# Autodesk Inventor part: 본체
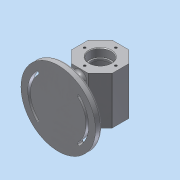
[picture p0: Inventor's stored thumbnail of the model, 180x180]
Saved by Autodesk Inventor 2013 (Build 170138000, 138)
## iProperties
Created: 2017-06
Part Number: 본체
Material: 알루미늄 6061
Document SubType Name: Modeling
Designer: dgall
Density: 2.71 g/cm^3
Mass: 562.296 g
Surface Area: 566.36 cm^2
Volume: 207.489 cm^3
Author: dgall
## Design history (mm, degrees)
sketch "스케치1"
  geometry: L1 (-30, 12.426)-(-12.426, 30); L2 (-12.426, 30)-(12.426, 30); L3 (12.426, 30)-(30, 12.426); L4 (30, 12.426)-(30, -12.426); L5 (30, -12.426)-(12.426, -30); L6 (12.426, -30)-(-12.426, -30); L7 (-12.426, -30)-(-30, -12.426); L8 (-30, -12.426)-(-30, 12.426); 2 further points
  constraints: 16 end point, 1 coincident, 1 vertical, 17 other
  dimensions: "d0" = 30 distance from line of L8 point (0, 0)
extrude "돌출1" new body sketch "스케치1" distance "d1" = 70; taper "d2" = 0 deg
sketch "스케치2"
  geometry: L1 (30, 70)-(12.426, 70) reference; L2 (12.426, 70)-(-12.426, 70) reference; L3 (12.426, 0)-(30, 0) reference; L4 (-12.426, 0)-(12.426, 0) reference; L5 (-30, 0)-(-12.426, 0) reference; L6 (-30, 0)-(-30, 70) reference; L7 (0, 0)-(0, 70); L8 (16, 58)-(14, 58); L9 (14, 58)-(14, 55); L10 (14, 55)-(22, 55); L11 (25, 52)-(25, 18); L12 (22, 15)-(14, 15); L13 (14, 15)-(14, 12); L14 (16, 70)-(16, 58); L15 (14, 12)-(16, 12); L16 (16, 12)-(16, 0); L17 (16, 70)-(30, 70); L18 (30, 0)-(16, 0); L19 (30, 0)-(30, 70); L20 (16, 70)-(0, 70); L21 (16, 0)-(0, 0); A1 r 3 centre (22, 52) between (25, 52) and (22, 55); A2 r 3 centre (22, 18) between (22, 15) and (25, 18)
  constraints: 30 end point, 4 collinear, 4 perpendicular, 4 point on circle, 4 point on line, 4 tangent, 3 parallel, 2 centre point, 2 vertical alignment, 1 equal radius, 1 midpoint
  dimensions: "d4" = 28 diameter of L9 L7; "d6" = 32 diameter of L14 L7; "d7" = 50 diameter of L11 L7; "d8" = 12 distance between parallel lines of L8 L2; "d10" = 40 distance between parallel lines of L12 L10; "d12" = 3 distance between parallel lines of L15 L12; "d13" = 3 radius of A1; "d14" = 60 diameter of L19 L7
revolve "회전1" sketch "스케치2" stored, may be unused: angle "d15" = 90 deg
node "작업 평면1"
sketch "스케치4"
  geometry: L1 (-30, 0)-(-30, 70) reference; L2 (30, 0)-(30, 70) reference; L3 (-12.426, 70)-(12.426, 70) reference; L4 (12.426, 0)-(-12.426, 0) reference; C1 r 55 at (0, 35); 2 further points
  constraints: 1 centre point, 1 midpoint, 1 vertical alignment
  dimensions: "d17" = 110 diameter of C1; "d18" = 35 distance from line of C1.centre L4
extrude "돌출2" join sketch "스케치4" distance "d19" = 10; taper "d20" = 0 deg
sketch "스케치6"
  geometry: L1 (30.406, 30.406)-(0, 0); L2 (0, 0)-(30.406, -30.406); L3 (0, 0)-(55, 0); A1 r 5 centre (30.406, 30.406) between (33.941, 33.941) and (26.87, 26.87); A2 r 48 centre (0, 0) between (33.941, -33.941) and (33.941, 33.941); A3 r 38 centre (0, 0) between (26.87, -26.87) and (26.87, 26.87); A4 r 5 centre (30.406, -30.406) between (26.87, -26.87) and (33.941, -33.941); A5 r 2 centre (30.406, 30.406) between (31.82, 31.82) and (28.991, 28.991); A6 r 41 centre (0, 0) between (28.991, -28.991) and (28.991, 28.991); A7 r 2 centre (30.406, -30.406) between (28.991, -28.991) and (31.82, -31.82); A8 r 45 centre (0, 0) between (31.82, -31.82) and (31.82, 31.82); 1 further point
  constraints: 16 point on circle, 8 centre point, 6 end point, 4 tangent, 2 coincident, 1 equal radius, 1 horizontal, 1 horizontal alignment, 1 perpendicular, 4 other
  dimensions: "d30" = 90 deg angle of L2 L1; "d31" = 45 deg angle of L3 L1; "d32" = 5 radius of A1; "d34" = 43 distance of L1.start L1.end; "d35" = 2 radius of A5
extrude "돌출3" cut sketch "스케치6" stored distance "d36" = 0; taper "d37" = 0 deg
extrude "돌출4" cut sketch "스케치6" distance "d38" = 3; taper "d39" = 0 deg
sketch "스케치7"
  geometry: L1 (-5, 24)-(-5, -24); L2 (5, -24)-(5, 24); A1 r 38 centre (0, 0) between (26.87, -26.87) and (26.87, 26.87) reference; A2 r 5 centre (0, -24) between (-5, -24) and (5, -24); A3 r 5 centre (0, 24) between (5, 24) and (-5, 24); 2 further points
  constraints: 4 end point, 4 point on circle, 4 tangent, 2 centre point, 2 vertical, 1 horizontal alignment, 1 midpoint, 1 vertical alignment
  dimensions: "d40" = 48 distance of A2.centre A3.centre; "d42" = 5 radius of A3
extrude "돌출5" join sketch "스케치7" stored distance "d43" = 0; taper "d44" = 0 deg
fillet "모깎기1" dims "d45" = 5
fillet "모깎기2" dims "d46" = 0.3
chamfer "모따기1" distance "d47" = 1; stored, may be unused: second distance "d48" = 2, angle "d49" = 45 deg
sketch "스케치8"
  geometry: C1 r 17 at (0, 0) reference; 1 further point
  constraints: 1 vertical alignment
  dimensions: "d50" = 23 distance of point (0, 23) C1.centre
hole "구멍1" sketch "스케치8" at (0, 23) diameter "d51" = 3.459; stored, may be unused: countersink angle "d55" = 90 deg, drill point angle "d57" = 118 deg; dims "d52" = 8, "d53" = 4, "d54" = 2, "d56" = 10
node "작업 평면2"
sketch "스케치9"
  geometry: L1 (42.426, 0)-(42.426, -70) reference; 2 further points
  constraints: 1 other
  dimensions: "d61" = 35 distance of point (12.426, -35) point (12.426, 0); "d62" = 30 distance from line of point (12.426, -35) L1
feature "엠보싱1" sketch "스케치9" dims "d0" = 30, "d4" = 28, "d6" = 32, "d7" = 50, "d8" = 12, "d10" = 40, "d12" = 3, "d13" = 3, "d14" = 60, "d63" = 0.5, "d64" = 0
sketch "스케치13"
  geometry: L1 (0, 0)-(-24.853, 0) reference; L2 (-42.426, 0)-(-42.426, 70) reference; C1 r 8 at (-12.426, 35); 1 further point
  constraints: 1 centre point
  dimensions: "d79" = 16 diameter of C1; "d80" = 35 distance from line of C1.centre L1; "d81" = 30 distance from line of C1.centre L2
extrude "돌출7" join sketch "스케치13" distance "d82" = 7; taper "d83" = 0 deg
sketch "스케치14"
  geometry: C1 r 8 at (0, 0) reference; 2 further points
  constraints: 1 coincident
hole "구멍3" sketch "스케치14" at (0, 0) diameter "d84" = 8; stored, may be unused: countersink angle "d88" = 90 deg, drill point angle "d90" = 118 deg; dims "d85" = 8, "d86" = 4, "d87" = 2, "d89" = 40
chamfer "모따기3" distance "d91" = 1; stored, may be unused: second distance "d92" = 2, angle "d93" = 45 deg
fillet "모깎기3" dims "d94" = 3
fillet "모깎기4" dims "d95" = 1
node "솔리드1"
mirror "대칭1"
pattern_circular "원형 패턴1" dims angle "d59" = 360 deg
mirror "대칭2"
other parameters: "d16" = -62, "d25" = 96
